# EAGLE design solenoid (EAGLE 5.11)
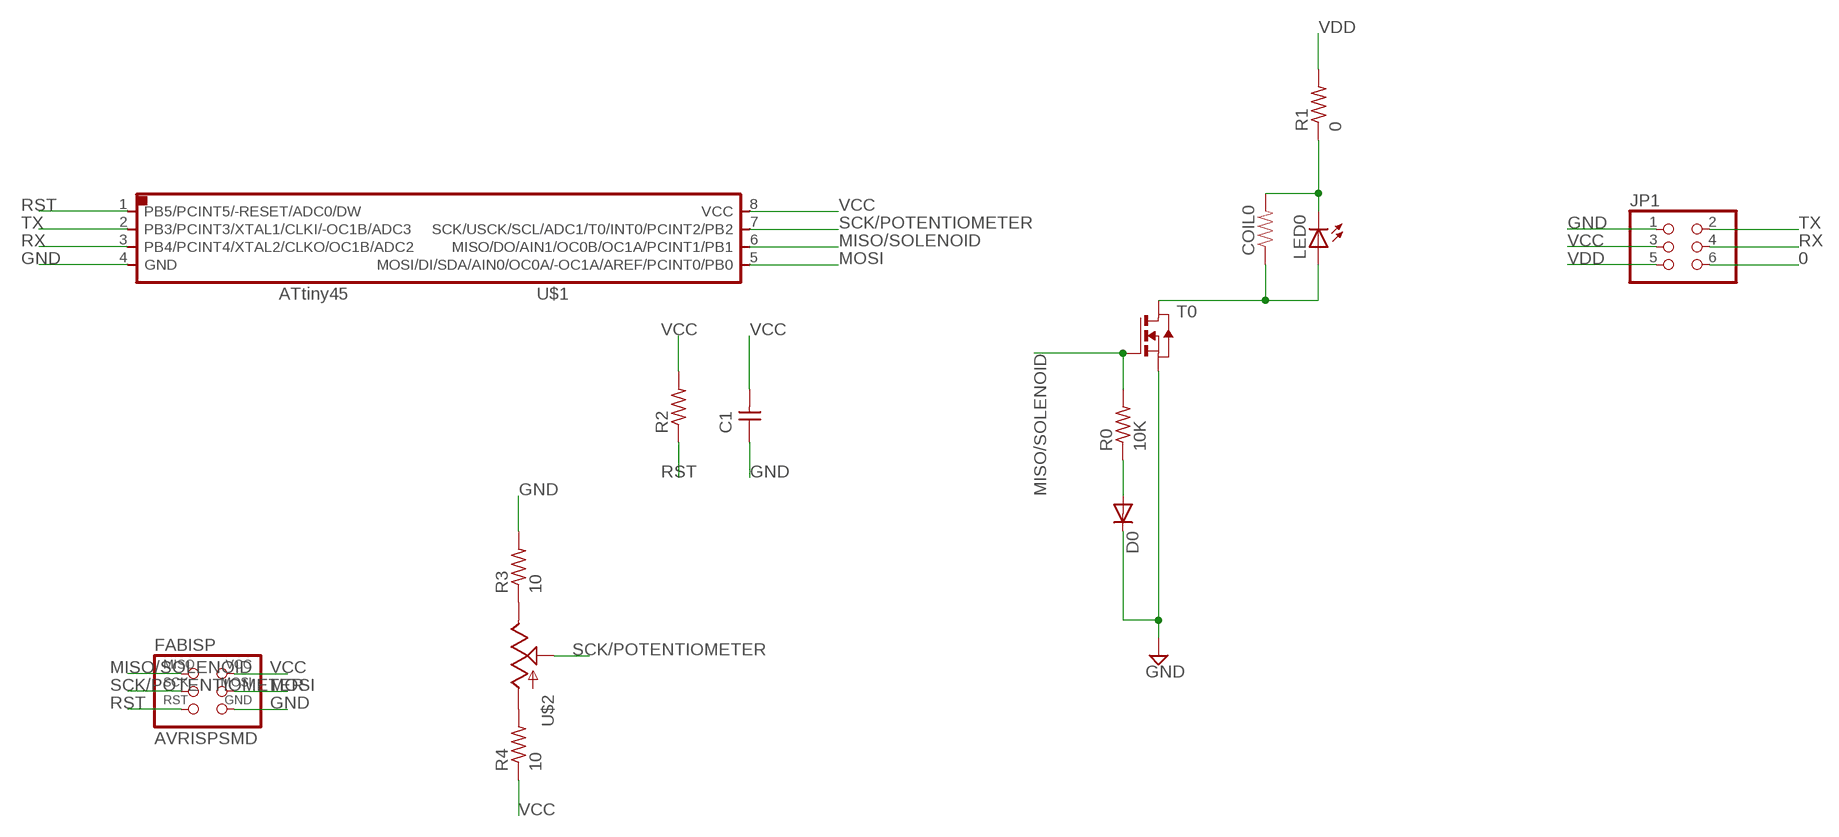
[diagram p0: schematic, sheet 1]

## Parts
C1  UNPOLARIZED_CAPACITOR1206  [1206]
COIL0  RESISTOR1206  [1206]
D0  DIODESOD123  [SOD123]
FABISP  AVRISPSMD  [2X03SMD]
JP1  PINHD-2X3-SMD  [2X03SMD]
LED0  LED1206  [1206]
R0  10K  RESISTOR1206  [1206]
R1  0  RESISTOR1206  [1206]
R2  RESISTOR1206  [1206]
R3  10  RESISTOR1206  [1206]
R4  10  RESISTOR1206  [1206]
T0  NMOSFETSOT23  [SOT-23]
U$1  ATTINY45SI  [SOIC8]
U$2  POT  [ALPS_POT]

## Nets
0: JP1.6
CO0: COIL0.1 LED0.1(A) T0.1(D)
GND: C1.1 D0.CATHODE(C) FABISP.6(GND) JP1.1 R3.2 T0.2(S) U$1.4(GND)
MISO/SOLENOID: FABISP.1(MISO) R0.2 T0.3(G) U$1.6(MISO/DO/AIN1/OC0B/OC1A/PCINT1/PB1)
MOSI: FABISP.4(MOSI) U$1.5(MOSI/DI/SDA/AIN0/OC0A/-OC1A/AREF/PCINT0/PB0)
N$1: COIL0.2 LED0.2(C) R1.1
N$2: R3.1 U$2.P$1(E)
N$3: R4.2 U$2.P$3(A)
R0: D0.ANODE(A) R0.1
RST: FABISP.5(RST) R2.1 U$1.1(PB5/PCINT5/-RESET/ADC0/DW)
RX: JP1.4 U$1.3(PB4/PCINT4/XTAL2/CLKO/OC1B/ADC2)
SCK/POTENTIOMETER: FABISP.3(SCK) U$1.7(SCK/USCK/SCL/ADC1/T0/INT0/PCINT2/PB2) U$2.P$2(S)
TX: JP1.2 U$1.2(PB3/PCINT3/XTAL1/CLKI/-OC1B/ADC3)
VCC: C1.2 FABISP.2(VCC) JP1.3 R2.2 R4.1 U$1.8(VCC)
VDD: JP1.5 R1.2

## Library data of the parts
C1 = ng:UNPOLARIZED_CAPACITOR: unpolarized_capacitor
COIL0 = SparkFun:RESISTOR: Resistor
D0 = ng:DIODE: DIODE
FABISP = fab:AVRISP
JP1 = fab:PINHD-2X3-SMD: PIN HEADER
LED0 = ng:LED
R0 R1-R4 = ng:RESISTOR
T0 = ng:NMOSFET: MOS FET
U$1 = fab:ATTINY45
U$2 = SparkFun:POT

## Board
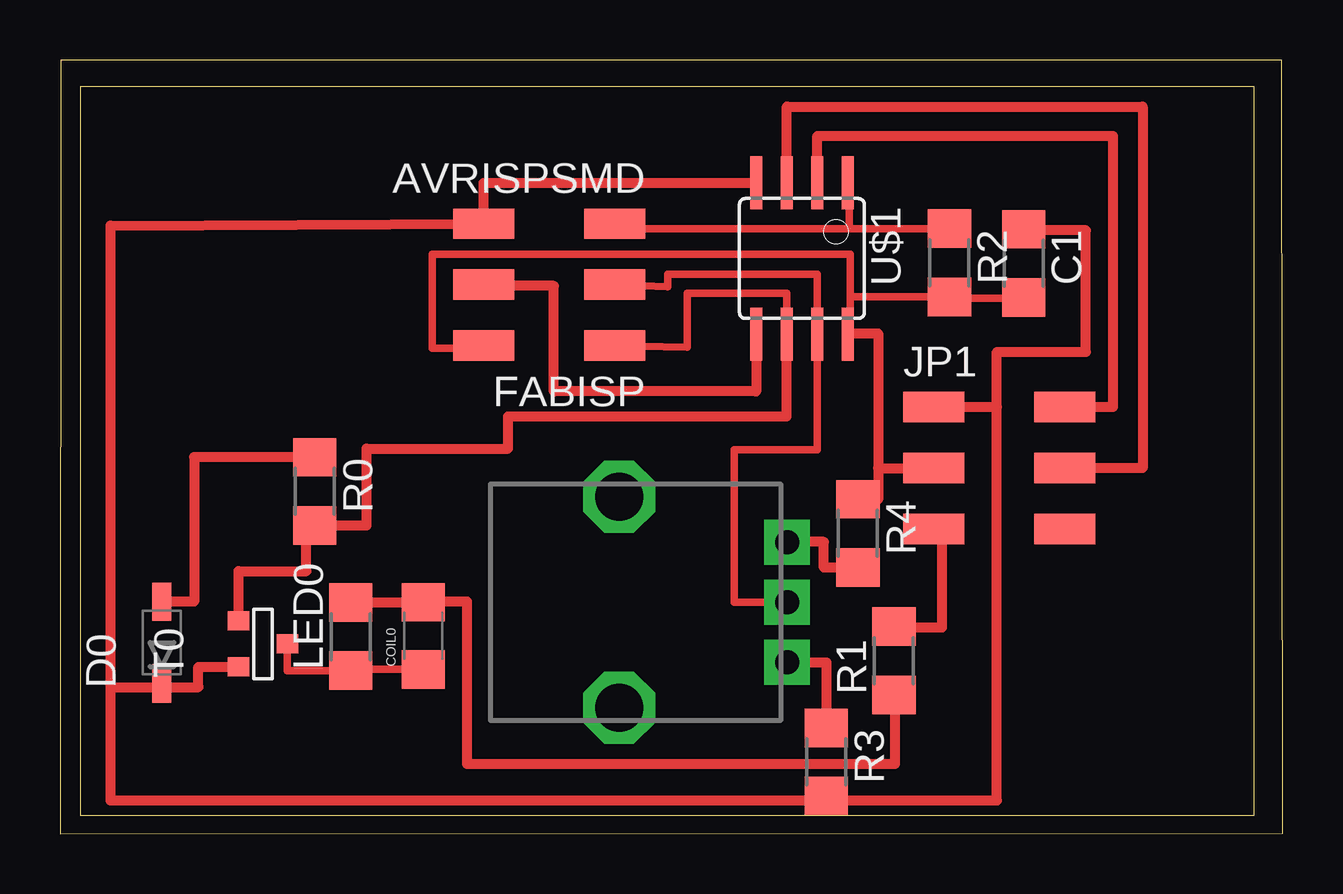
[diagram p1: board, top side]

Size 50.95 x 32.25 mm. Coordinates in mm from the lower left corner, seen from the top.
Outline: 0,0 50.95,0.03 50.9,32.25 0.03,32.25 0,0
Copper layers (1*16): Top 0.035mm / dielectric 1.5mm / Bottom 0.035mm
Design rules "default": minimum track width 10mil, minimum drill 24mil, track to track 8mil, track to pad 8mil, pad to pad 8mil, via to via 8mil, smd to smd 8mil, copper to edge 40mil, drill to drill 8mil, minimum pad ring 10mil, minimum via ring 8mil, stop-mask expansion 4mil, vias tented up to drill 0mil, thermal gap 10mil
Milling: area 0.8,0.8 to 49.8,31.1

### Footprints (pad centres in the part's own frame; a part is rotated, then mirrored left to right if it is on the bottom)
1206 = smd 1.6 x 1.803: 1 -1.422,0; 2 1.422,0
1206' = smd 1.6 x 1.8: 1 -1.4,0; 2 1.4,0
SOD123 = smd 1.6 x 0.8: ANODE 1.7,0; CATHODE -1.7,0
2X03SMD = smd 2.54 x 1.27: 1 -2.54,2.54; 2 2.92,2.54; 3 -2.54,0; 4 2.92,0; 5 -2.54,-2.54; 6 2.92,-2.54
SOT-23 = smd 0.787 x 0.889: 1 0.025,-1.016; 2 -0.94,1.016; 3 0.991,1.016
SOIC8 = smd 0.5 x 2.2: 1 -1.905,-3.154; 2 -0.645,-3.154; 3 0.625,-3.154; 4 1.895,-3.154; 5 1.905,3.154; 6 0.635,3.154; 7 -0.635,3.154; 8 -1.905,3.154
ALPS_POT = drill 1 pad 1.88 square: P$1 7,-2.5; P$2 7,0; P$3 7,2.5 | drill 2 octagon: P$4 0,-4.4; P$5 0,4.4

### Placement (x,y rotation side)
C1  40.16,23.77 270 top
COIL0  [1206']  15.14,8.26 90 top
D0  4.24,7.98 90 top
FABISP  20.57,22.89 180 top
JP1  38.94,15.24 0 top
LED0  12.12,8.23 90 top
R0  10.62,14.27 270 top
R1  34.75,7.21 90 top
R2  37.06,23.8 270 top
R3  31.93,3 270 top
R4  33.25,12.52 270 top
T0  8.46,7.9 90 top
U$1  30.91,23.98 180 top
U$2  23.29,9.65 0 top

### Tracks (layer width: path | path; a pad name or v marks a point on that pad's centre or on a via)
CO0
  Top 0.305: COIL0.1 12.12,6.86 LED0.1 9.47,6.81 T0.1
GND
  Top 0.305: T0.2 7.52,6.96
  Top 0.406: T0.2 5.77,6.96 5.77,6.12 4.24,6.12 | 4.24,6.12 D0.CATHODE | 2.11,6.12 2.11,25.35 FABISP.6 17.65,27.13 U$1.4 | 31.98,1.4 2.11,1.4 2.11,6.12 | 31.98,1.4 39.04,1.4 39.04,17.78 | 39.04,17.78 39.04,20.09 42.75,20.09 42.75,25.15 40.16,25.15 C1.1 | 39.04,17.78 JP1.1 | 2.11,6.12 4.24,6.12 | R3.2 31.98,1.57 31.98,1.4
MISO/SOLENOID
  Top 0.305: FABISP.1 26.14,20.27 26.14,22.53 30.28,22.53 U$1.6
  Top 0.406: U$1.6 30.28,17.4 18.67,17.4 18.67,16.05 12.78,16.05 12.78,12.85 R0.2 10.26,12.85 10.26,10.95 7.44,10.95 T0.3
MOSI
  Top 0.406: U$1.5 29.01,18.44 20.57,18.44 20.57,22.84 17.65,22.84 FABISP.4
N$1
  Top 0.406: R1.1 34.8,5.79 34.8,2.92 16.97,2.92 16.97,9.68 15.14,9.68 COIL0.2 LED0.2
N$2
  Top 0.406: U$2.P$1 31.93,7.15 R3.1
N$3
  Top 0.406: R4.2 31.83,11.1 31.83,12.17 30.29,12.17 U$2.P$3
R0
  Top 0.406: R0.1 5.59,15.7 5.59,9.68 D0.ANODE
RST
  Top 0.305: 32.89,25.22 23.11,25.22 FABISP.5 | 32.89,25.22 R2.1 | U$1.1 32.89,27.13 32.89,25.22
RX
  Top 0.406: JP1.4 45.11,15.24 45.11,30.3 30.29,30.3 U$1.3
SCK/POTENTIOMETER
  Top 0.305: FABISP.3 25.32,22.81 25.32,23.32 31.55,23.32 U$1.7 31.55,16 28.09,16 28.09,9.65 U$2.P$2
TX
  Top 0.406: JP1.2 43.87,17.78 43.87,29.08 31.56,29.08 U$1.2
VCC
  Top 0.305: 32.92,20.82 U$1.8 | 32.92,22.38 32.92,24.16 15.52,24.16 15.52,20.24 17.65,20.24 FABISP.2 | 32.92,22.38 R2.2 37.11,22.38 37.11,22.33 40.16,22.33 C1.2 | 32.92,22.38 32.92,20.82 | 32.92,20.82 33.12,20.82
  Top 0.406: 34.09,15.24 JP1.3 | 34.09,15.24 34.09,20.85 32.82,20.85 U$1.8 | R4.1 34.09,13.94 34.09,15.24
VDD
  Top 0.406: JP1.5 36.75,12.7 36.75,8.61 34.75,8.61 R1.2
